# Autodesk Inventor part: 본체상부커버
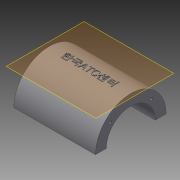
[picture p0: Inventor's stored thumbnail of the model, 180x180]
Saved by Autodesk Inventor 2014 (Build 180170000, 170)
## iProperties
Created: 2015-12
Part Number: 본체상부커버
Material: 일반
Document SubType Name: Modeling
Designer: mduedu
Density: 2.71 g/cm^3
Appearance: 기본값
Author: mduedu
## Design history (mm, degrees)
sketch "스케치1"
  geometry: L1 (45, 40)-(-45, 40); L2 (-45, 40)-(-45, -40); L3 (-45, -40)-(45, -40); L4 (45, -40)-(45, 40); L5 (45, 40)-(-45, -40); L6 (-45, 40)-(45, -40); 2 further points
  constraints: 12 end point, 2 midpoint, 2 parallel, 1 coincident, 1 horizontal, 1 perpendicular, 3 other
  dimensions: "d0" = 90 distance of L2.end L3.end; "d2" = 80 distance of L1.end L2.end
extrude "돌출1" new body sketch "스케치1" distance "d3" = 10; taper "d4" = 0 deg
sketch "스케치2"
  geometry: C1 r 32.5 at (80, 0); 1 further point
  constraints: 1 centre point
  dimensions: "d5" = 65 diameter of C1; "d116" = 80 distance of point (0, 0) C1.centre
extrude "돌출2" join sketch "스케치2" stored distance "d7" = 75; taper "d8" = 0 deg
sketch "스케치3"
  geometry: L1 (-27.5, -20)-(27.5, -20); L2 (27.5, -20)-(27.5, 20); L3 (27.5, 20)-(-27.5, 20); L4 (-27.5, 20)-(-27.5, -20); L5 (-27.5, -20)-(27.5, 20); L6 (27.5, -20)-(-27.5, 20); 1 further point
  constraints: 12 end point, 2 midpoint, 2 parallel, 1 horizontal, 1 perpendicular
  dimensions: "d9" = 55 distance of L2.end L3.end; "d11" = 40 distance of L1.end L2.end
extrude "돌출3" new body sketch "스케치3" stored distance "d12" = 75; taper "d13" = 0 deg
fillet "모깎기1"
fillet "모깎기2"
feature "결합1"
  node "솔리드2"
sketch "스케치4"
  geometry: L1 (-37.5, 47.5)-(37.5, 47.5) reference; L2 (32.5, 47.5)-(40.208, 10); L3 (37.5, 47.5)-(37.5, 112.5) reference; L4 (60.208, 0)-(60.208, 10) reference; L5 (60.208, 10)-(-60.208, 10) reference; 1 further point
  constraints: 2 end point, 2 point on line
  dimensions: "d15" = 5 distance from line of L2.start L3; "d117" = 20 distance from line of L2.end L4
sketch "스케치5"
  geometry: L1 (10, 35.208)-(56.729, 22.687); L2 (0, 60.208)-(10, 60.208) reference; L3 (10, -60.208)-(10, 60.208) reference; 2 further points
  constraints: 2 end point, 1 point on line, 2 other
  dimensions: "d118" = 25 distance from line of L1.start L2; "d119" = 75 deg angle of L1 L3
feature "리브1" dims "d19" = 1, "d20" = 6, "d21" = 0, "d22" = 0, "d23" = 1, "d24" = 1
feature "리브2" dims "d25" = 1, "d26" = 6, "d27" = 0, "d28" = 0, "d29" = 1, "d30" = 1
fillet "모깎기4" dims "d31" = 2
fillet "모깎기5" dims "d32" = 2
fillet "모깎기6" dims "d33" = 2
sketch "스케치6"
  geometry: L1 (0, 0)-(-32.88, 32.88); L2 (0, 0)-(-46.5, 0); A1 r 46.5 centre (0, 0) between (-32.88, 32.88) and (-46.5, 0); 5 further points
  constraints: 4 end point, 2 coincident, 2 point on circle, 1 centre point, 1 horizontal, 5 other
  dimensions: "d120" = 93 diameter of A1; "d122" = 45 deg angle of L1 L2; "d126" = 360 deg dimension on point (0, 0) point (-32.88, 32.88) (derived)
hole "구멍1" sketch "스케치6" at (-32.88, 32.88), (-32.88, -32.88), (32.88, -32.88), (32.88, 32.88) diameter "d34" = 7; stored, may be unused: countersink angle "d38" = 90 deg, drill point angle "d40" = 118 deg; dims "d35" = 6, "d36" = 12, "d37" = 3, "d39" = 8
fillet "모깎기13" dims "d131" = 3
hole "구멍2" diameter "d44" = 45; stored, may be unused: countersink angle "d48" = 90 deg, drill point angle "d50" = 118 deg; dims "d42" = 10, "d43" = 10, "d45" = 6, "d46" = 4, "d47" = 2, "d49" = 8
sketch "스케치7" dims "d52" = 26.5
  geometry: L1 (0, 0)-(32.5, 0); L2 (0, 0)-(22.981, 22.981); A1 r 32.5 centre (0, 0) between (32.5, 0) and (22.981, 22.981) reference; 3 further points
  constraints: 4 end point, 2 point on circle, 1 coincident, 1 horizontal, 1 point on line, 3 other
  dimensions: "d51" = 45 deg angle of L2 L1
hole "구멍3" sketch "스케치7" at (18.738, 18.738) diameter "d54" = 2.459; stored, may be unused: countersink angle "d58" = 90 deg, drill point angle "d60" = 118 deg; dims "d55" = 8, "d56" = 4, "d57" = 2, "d59" = 10
sketch "스케치9"
  geometry: L1 (-75, -110)-(75, -110); L2 (75, -110)-(75, 0); L3 (75, 0)-(-75, 0); L4 (-75, 0)-(-75, -110); L5 (-60.208, -80)-(60.208, -80) reference; C1 r 32.5 at (0, 0) reference; 2 further points
  constraints: 8 end point, 2 parallel, 1 coincident, 1 horizontal, 1 midpoint, 1 perpendicular
  dimensions: "d148" = 30 distance between parallel lines of L5 L1; "d159" = 150 distance between parallel lines of L2 L4
extrude "돌출5" cut sketch "스케치9" stored distance "d73" = 0; taper "d74" = 0 deg
node "작업 평면3"
sketch "스케치17" dims "d2" = 80
  geometry: 2 further points
  constraints: 1 coincident, 1 other
feature "엠보싱1" sketch "스케치17" dims "d0" = 90, "d2" = 80, "d150" = 0.5, "d151" = 0
node "솔리드1"
mirror "대칭1"
mirror "대칭2"
pattern_circular "원형 패턴1" dims angle "d62" = 360 deg
mirror "대칭3"
